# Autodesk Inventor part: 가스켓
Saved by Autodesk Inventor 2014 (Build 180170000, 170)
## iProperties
Created: 2025-10
Part Number: 가스켓
Material: 일반
Document SubType Name: Modeling
Designer: dg
Density: 1 g/cm^3
Appearance: 기본값
Author: dg
Author: jhkim
Creation Date: 2025-10-01
Sending System: Autodesk Inventor 2026
Preprocessor: ST-DEVELOPER v20.1
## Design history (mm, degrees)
node "가스켓1"
node "솔리드1"
node "기준1"
